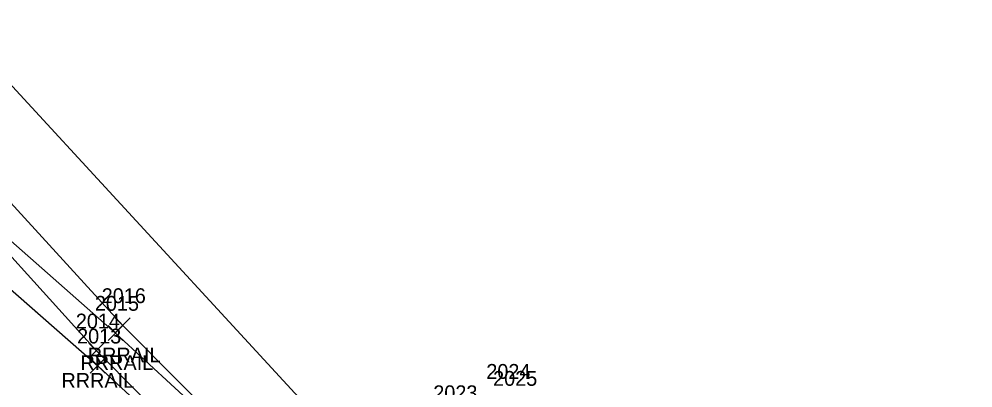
# Model space of a CAD drawing. Extents: x 1635588 to 1637550, y 621583 to 623638.
# Drawn here: x 1637037.4 to 1637166, y 621894.7 to 621944.5 of the extents above; entities that cross this region are included whole.
import ezdxf

# ---------------------------------------------------------------- set-up
doc = ezdxf.new("R2010")
doc.units = 0
for name, color, linetype in [('L_I', 7, 'Continuous'), ('LBC', 7, 'Continuous'), ('R_A', 7, 'Continuous'), ('R_I', 7, 'Continuous'), ('R_TIC', 7, 'Continuous'), ('RR', 7, 'Continuous')]:
    doc.layers.add(name, color=color, linetype=linetype)

msp = doc.modelspace()

# ---------------------------------------------------------------- linework, layer by layer
at = {"layer": 'LBC'}
msp.add_lwpolyline([(1636885.66, 622098.09), (1636886.49, 622098.53), (1637000.47, 621974.51), (1637086.58, 621881), (1637094.62, 621887.96), (1637096.59, 621890.08)], dxfattribs=at)
at = {"layer": 'R_TIC'}
for points in [[(1637050.37, 621902.17), (1637052.37, 621904.17)], [(1637052.37, 621902.17), (1637050.37, 621904.17)], [(1637049.39, 621901.14), (1637051.39, 621903.14)], [(1637051.39, 621901.14), (1637049.39, 621903.14)], [(1637046.82, 621898.75), (1637048.82, 621900.75)], [(1637048.82, 621898.75), (1637046.82, 621900.75)], [(1637047, 621896.73), (1637049, 621898.73)], [(1637049, 621896.73), (1637047, 621898.73)]]:
    msp.add_lwpolyline(points, dxfattribs=at)
at = {"layer": 'RR'}
for points in [[(1636647.57, 622303.46), (1636681.53, 622274.07), (1636698.35, 622258.6), (1636736.07, 622216.66), (1636772.81, 622171.31), (1636793.48, 622145.5), (1636799.12, 622138.4), (1636815.41, 622118.42), (1636845.94, 622085.12), (1636908.55, 622026.21), (1636983.07, 621959.74), (1637027.08, 621922.66), (1637050.39, 621902.14), (1637074.4, 621880.01)], [(1636645.23, 622298.69), (1636678.25, 622270.68), (1636695.49, 622253.83), (1636732.46, 622213.3), (1636769.51, 622167.71), (1636788.83, 622143.09), (1636795.06, 622135.55), (1636811.52, 622115.54), (1636841.96, 622081.95), (1636905.16, 622022.78), (1636979.87, 621956.02), (1637024.02, 621918.73), (1637048, 621897.73), (1637071.19, 621876.23)], [(1637026.25, 621930.62), (1637051.37, 621903.17), (1637074.4, 621880.01), (1637083.38, 621871.59), (1637115.01, 621842.98), (1637140.82, 621820.97), (1637163.57, 621803.06), (1637178.63, 621791.62), (1637197.58, 621777.98), (1637205.69, 621772.14), (1637224.52, 621759.19), (1637253.9, 621739.72), (1637289.58, 621717.58), (1637320.59, 621699.03)], [(1637027.08, 621922.66), (1637047.82, 621899.75), (1637071.19, 621876.23), (1637080.21, 621867.76), (1637112.17, 621839), (1637137.72, 621817.24), (1637160.21, 621799.22), (1637175.91, 621787.14), (1637194.67, 621774), (1637203.09, 621767.92), (1637221.71, 621755.12), (1637251.64, 621735.37), (1637287.01, 621713.34), (1637318.07, 621694.59)]]:
    msp.add_lwpolyline(points, dxfattribs=at)

# ---------------------------------------------------------------- texts
at = {"layer": 'L_I'}
for s, p in [('2024', (1637100.41, 621895.96)), ('2023', (1637093.26, 621893.08))]:
    msp.add_text(s, height=2, dxfattribs=at).set_placement(p)
at = {"layer": 'R_A'}
for p in [(1637046.66, 621898.17), (1637045.68, 621897.14), (1637043.11, 621894.75)]:
    msp.add_text('RRRAIL', height=2, dxfattribs=at).set_placement(p)
at = {"layer": 'R_I'}
for s, p in [('2016', (1637048.54, 621906.17)), ('2015', (1637047.62, 621905.14)), ('2014', (1637045.05, 621902.75)), ('2013', (1637045.22, 621900.73)), ('2025', (1637101.33, 621895.02))]:
    msp.add_text(s, height=2, dxfattribs=at).set_placement(p)

doc.saveas('drawing.dxf')
